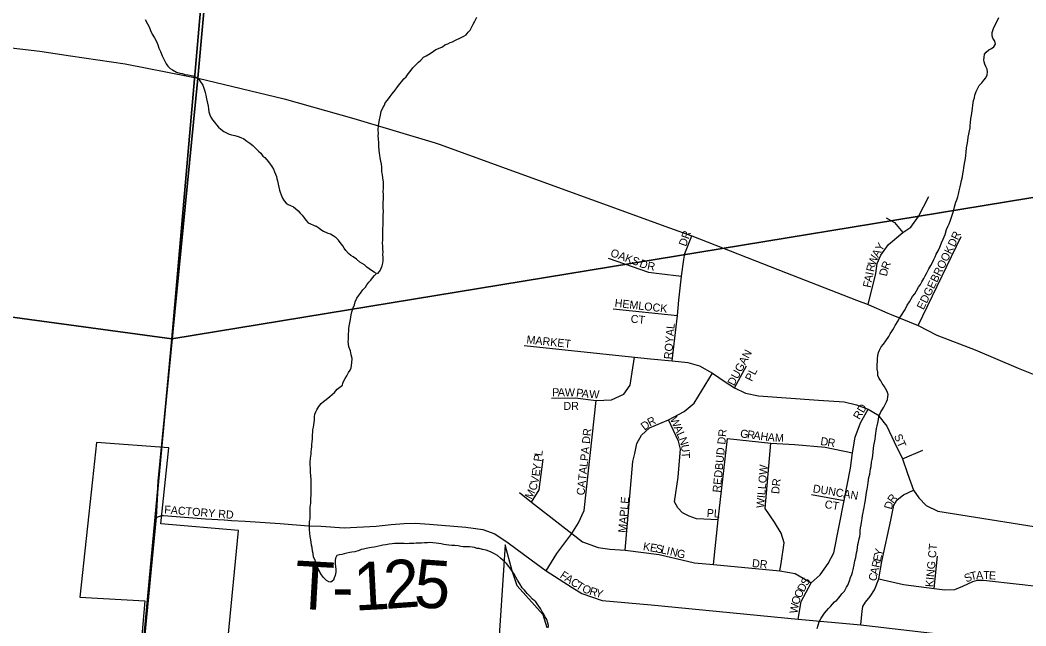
# Model space of a CAD drawing. Extents: x 0 to 1064, y 0 to 440.
# Drawn here: x 203.49 to 222.52, y 369.72 to 381.17 of the extents above; entities that cross this region are included whole.
import ezdxf

# ---------------------------------------------------------------- set-up
doc = ezdxf.new("R2010")
doc.units = 0
for name, color, linetype in [('GM_X_City_Street', 7, 'Continuous'), ('GM_X_City_Street_Text', 7, 'Continuous'), ('GM_X_Corporation', 7, 'Continuous'), ('GM_X_Minor_River', 7, 'Continuous'), ('GM_X_Section', 7, 'Continuous'), ('GM_X_State_Route', 7, 'Continuous'), ('GM_X_Township', 7, 'Continuous'), ('GM_X_Township_Road', 7, 'Continuous'), ('GM_X_Township_Road_Text', 7, 'Continuous')]:
    doc.layers.add(name, color=color, linetype=linetype)

msp = doc.modelspace()

# ---------------------------------------------------------------- linework, layer by layer
at = {"layer": 'GM_X_City_Street'}
for points in [[(206.883, 380.385), (207.047, 382.236), (207.264, 384.616)], [(206.856, 380.071), (206.883, 380.385)], [(219.537, 375.79), (219.682, 376.377), (219.704, 376.567), (219.779, 376.725), (219.921, 376.926), (220.193, 377.153), (220.342, 377.257), (220.489, 377.453), (220.683, 377.833)], [(219.878, 377.431), (220.034, 377.343), (220.193, 377.153)], [(215.83, 374.729), (215.931, 375.582), (215.954, 375.873), (216.002, 376.331), (216.046, 376.645), (216.07, 376.754), (216.199, 377.09)], [(220.48, 375.396), (221.299, 377.078)], [(214.617, 376.667), (215.378, 376.405), (215.583, 376.376), (216.002, 376.331)], [(214.714, 375.71), (215.931, 375.582)], [(213.03, 375.02), (215.114, 374.794), (215.416, 374.763), (215.83, 374.729), (216.127, 374.694), (216.344, 374.631), (216.589, 374.496), (216.833, 374.333), (217.008, 374.216), (217.217, 374.119), (217.462, 374.069), (218.595, 373.983), (219.084, 373.952), (219.317, 373.898), (219.534, 373.812), (219.717, 373.704), (219.887, 373.49), (220.027, 373.199), (220.186, 372.873), (220.283, 372.596), (220.394, 372.283), (220.495, 372.136), (220.636, 371.992), (220.852, 371.888), (222.838, 371.568)], [(213.542, 374.022), (213.992, 374.03), (214.388, 373.976), (214.679, 373.991), (214.912, 374.1), (215.032, 374.268), (215.07, 374.514), (215.114, 374.794)], [(217.008, 374.216), (217.233, 374.635)], [(214.939, 371.146), (215.085, 372.825), (215.119, 372.977), (215.16, 373.168), (215.25, 373.324), (215.401, 373.459), (215.758, 373.615), (216.053, 373.77), (216.247, 373.925), (216.589, 374.496)], [(213.441, 370.76), (213.645, 371.086), (213.928, 371.466), (214.056, 371.664), (214.16, 371.901), (214.388, 373.976)], [(218.211, 369.846), (218.269, 370.176), (218.455, 370.533), (218.626, 370.68), (218.781, 370.894), (218.886, 371.096), (219.084, 372.089), (219.2, 372.699), (219.243, 372.988), (219.289, 373.287), (219.389, 373.558), (219.534, 373.812)], [(216.701, 371.724), (216.286, 371.744), (216.15, 371.79), (216.022, 371.856), (215.933, 371.946), (215.871, 372.061), (215.94, 372.528), (215.967, 372.838), (215.987, 373.056), (215.948, 373.207), (215.758, 373.615)], [(216.612, 370.875), (216.701, 371.724), (216.876, 373.258)], [(216.876, 373.258), (217.695, 373.172), (218.149, 373.149), (218.723, 373.094), (219.243, 372.988)], [(217.868, 370.755), (217.889, 370.899), (217.947, 371.286), (217.889, 371.468), (217.761, 371.678), (217.59, 371.934), (217.695, 373.172)], [(220.186, 372.873), (220.571, 373.038)], [(213.169, 372.058), (213.313, 372.291), (213.384, 372.867)], [(219.398, 369.737), (219.423, 369.993), (219.437, 370.081), (219.484, 370.164), (219.577, 370.271), (219.655, 370.401), (219.736, 370.605), (219.792, 370.933), (219.967, 371.715), (220.023, 372), (220.085, 372.099), (220.204, 372.196), (220.394, 372.283)], [(212.936, 372.237), (213.169, 372.058), (213.701, 371.639), (213.928, 371.466), (214.128, 371.305), (214.427, 371.201), (214.648, 371.17), (214.939, 371.146), (215.579, 371.065), (216.251, 370.909), (216.612, 370.875), (217.868, 370.755), (218.153, 370.708), (218.455, 370.533)], [(218.463, 372.198), (219.084, 372.089)], [(206.203, 371.801), (207, 371.744), (207.349, 371.721)], [(212.727, 371.29), (213.16, 370.968), (213.441, 370.76), (213.938, 370.44), (214.116, 370.327), (214.501, 370.199), (215.432, 370.114), (218.211, 369.846), (219.398, 369.737), (221.24, 369.524), (222.354, 369.36), (222.97, 369.308), (223.022, 369.302)], [(220.782, 370.426), (220.848, 371.032)], [(219.736, 370.605), (220.204, 370.498), (220.782, 370.426), (220.988, 370.397), (221.178, 370.407), (221.327, 370.469), (221.514, 370.558), (221.605, 370.582), (221.719, 370.58), (222.395, 370.506), (222.456, 370.499)], [(222.456, 370.499), (223.084, 370.424), (223.105, 370.422)]]:
    msp.add_lwpolyline(points, dxfattribs=at)
at = {"layer": 'GM_X_Corporation'}
for points in [[(207.425, 369.505), (207.622, 371.519), (206.153, 371.646), (206.304, 373.08), (204.937, 373.184), (204.859, 372.476), (204.62, 370.26), (205.847, 370.19), (205.364, 364.533)], [(213.461, 369.682), (213.385, 369.928), (212.894, 370.475), (212.8, 370.759), (212.668, 371.25), (212.523, 369.059)]]:
    msp.add_lwpolyline(points, dxfattribs=at)
at = {"layer": 'GM_X_Minor_River'}
for points in [[(210.255, 376.373), (210.287, 376.415), (210.318, 376.463), (210.338, 376.523), (210.351, 376.572), (210.359, 376.626), (210.36, 376.681), (210.356, 376.736), (210.357, 376.785), (210.352, 376.834), (210.353, 376.894), (210.349, 376.961), (210.35, 377.01), (210.353, 377.101), (210.354, 377.144), (210.356, 377.217), (210.358, 377.302), (210.359, 377.345), (210.361, 377.424), (210.362, 377.485), (210.364, 377.546), (210.36, 377.625), (210.361, 377.68), (210.362, 377.722), (210.364, 377.789), (210.366, 377.868), (210.362, 377.935), (210.363, 377.984), (210.365, 378.069), (210.366, 378.112), (210.356, 378.179), (210.345, 378.252), (210.335, 378.301), (210.336, 378.35), (210.331, 378.393), (210.326, 378.447), (210.315, 378.503), (210.305, 378.564), (210.294, 378.613), (210.289, 378.655), (210.284, 378.71), (210.28, 378.777), (210.276, 378.851), (210.271, 378.924), (210.267, 378.979), (210.268, 379.027), (210.263, 379.088), (210.272, 379.179), (210.287, 379.282), (210.307, 379.373), (210.321, 379.44), (210.353, 379.512), (210.385, 379.56), (210.398, 379.602), (210.442, 379.656), (210.492, 379.722), (210.53, 379.776), (210.587, 379.847), (210.631, 379.907), (210.675, 379.961), (210.706, 380.003), (210.75, 380.056), (210.794, 380.098), (210.832, 380.152), (210.869, 380.199), (210.92, 380.265), (210.97, 380.319), (211.026, 380.372), (211.075, 380.413), (211.125, 380.467), (211.175, 380.49), (211.249, 380.537), (211.311, 380.578), (211.354, 380.613), (211.409, 380.63), (211.483, 380.665), (211.527, 380.7), (211.582, 380.717), (211.625, 380.747), (211.668, 380.758), (211.729, 380.787), (211.822, 380.833), (211.883, 380.862), (211.927, 380.891), (211.97, 380.939), (212.008, 380.98), (212.04, 381.041), (212.065, 381.089), (212.091, 381.149), (212.13, 381.221)], [(221.158, 377.585), (221.171, 377.64), (221.198, 377.724), (221.211, 377.773), (221.231, 377.827), (221.244, 377.875), (221.258, 377.942), (221.278, 378.015), (221.292, 378.075), (221.305, 378.136), (221.319, 378.208), (221.327, 378.263), (221.34, 378.323), (221.348, 378.378), (221.355, 378.42), (221.363, 378.487), (221.377, 378.554), (221.384, 378.608), (221.392, 378.675), (221.4, 378.754), (221.408, 378.815), (221.422, 378.888), (221.429, 378.954), (221.443, 379.015), (221.451, 379.076), (221.464, 379.13), (221.465, 379.173), (221.473, 379.227), (221.481, 379.306), (221.489, 379.367), (221.496, 379.409), (221.503, 379.452), (221.51, 379.5), (221.518, 379.561), (221.525, 379.603), (221.532, 379.646), (221.546, 379.7), (221.553, 379.749), (221.579, 379.821), (221.605, 379.869), (221.637, 379.929), (221.687, 379.983), (221.724, 380.031), (221.762, 380.078), (221.788, 380.132), (221.795, 380.187), (221.785, 380.242), (221.761, 380.291), (221.744, 380.334), (221.733, 380.377), (221.728, 380.42), (221.729, 380.463), (221.737, 380.523), (221.768, 380.565), (221.818, 380.607), (221.873, 380.63), (221.917, 380.665), (221.948, 380.713), (221.932, 380.768), (221.897, 380.83), (221.88, 380.873), (221.881, 380.934), (221.907, 381.012), (221.94, 381.078), (221.965, 381.126), (222.01, 381.217)], [(205.854, 381.182), (205.901, 381.095), (205.93, 381.04), (205.959, 380.972), (205.988, 380.905), (206.035, 380.831), (206.076, 380.751), (206.104, 380.683), (206.116, 380.64), (206.144, 380.573), (206.179, 380.493)], [(206.179, 380.493), (206.208, 380.432), (206.225, 380.389), (206.255, 380.339), (206.284, 380.296), (206.326, 380.253), (206.374, 380.227), (206.446, 380.183), (206.512, 380.163), (206.56, 380.156), (206.609, 380.143), (206.669, 380.136), (206.723, 380.122), (206.766, 380.115), (206.814, 380.09), (206.856, 380.065), (206.891, 380.021), (206.944, 379.941), (206.961, 379.898), (206.978, 379.843), (206.99, 379.8), (207.001, 379.751), (207.017, 379.678), (207.034, 379.598), (207.045, 379.543), (207.056, 379.488), (207.06, 379.433), (207.077, 379.378), (207.101, 379.335), (207.13, 379.28), (207.165, 379.236), (207.207, 379.187), (207.242, 379.143), (207.29, 379.106), (207.344, 379.062), (207.392, 379.037), (207.446, 379.011), (207.488, 378.998), (207.554, 378.984), (207.615, 378.971), (207.663, 378.952), (207.723, 378.926), (207.777, 378.882), (207.837, 378.844), (207.89, 378.801), (207.938, 378.751), (208.003, 378.689), (208.045, 378.651), (208.08, 378.596), (208.122, 378.57), (208.157, 378.527), (208.211, 378.465), (208.252, 378.403), (208.281, 378.348), (208.304, 378.299), (208.322, 378.256), (208.339, 378.213), (208.344, 378.17), (208.361, 378.127), (208.372, 378.066), (208.383, 378.011), (208.4, 377.956), (208.411, 377.913), (208.428, 377.864), (208.457, 377.803), (208.487, 377.753), (208.522, 377.71), (208.564, 377.685), (208.606, 377.665), (208.66, 377.64), (208.702, 377.609), (208.75, 377.565), (208.791, 377.521), (208.827, 377.478), (208.862, 377.429), (208.897, 377.385), (208.939, 377.336), (209.086, 377.273)], [(219.415, 371.707), (219.422, 371.749), (219.429, 371.804), (219.443, 371.858), (219.45, 371.9), (219.458, 371.955), (219.472, 372.028), (219.485, 372.094), (219.493, 372.149), (219.5, 372.197), (219.507, 372.24), (219.515, 372.3), (219.529, 372.379), (219.536, 372.428), (219.551, 372.525), (219.565, 372.585), (219.58, 372.688), (219.593, 372.731), (219.601, 372.81), (219.614, 372.864), (219.622, 372.931), (219.631, 373.016), (219.638, 373.07), (219.645, 373.125), (219.653, 373.186), (219.667, 373.246), (219.674, 373.307), (219.682, 373.355), (219.689, 373.404), (219.696, 373.446), (219.704, 373.501), (219.724, 373.579), (219.731, 373.622), (219.738, 373.67), (219.758, 373.719), (219.777, 373.761), (219.803, 373.803), (219.834, 373.851), (219.86, 373.899), (219.885, 373.953), (219.899, 373.995), (219.906, 374.044), (219.913, 374.092), (219.896, 374.147), (219.867, 374.203), (219.838, 374.246), (219.803, 374.296), (219.774, 374.351), (219.745, 374.395), (219.722, 374.45), (219.717, 374.511), (219.707, 374.572), (219.708, 374.615), (219.709, 374.657), (219.71, 374.712), (219.712, 374.767), (219.719, 374.827), (219.733, 374.888), (219.752, 374.93), (219.784, 374.99), (219.828, 375.044), (219.872, 375.104), (219.929, 375.187), (219.955, 375.235), (220.005, 375.313), (220.031, 375.355), (220.05, 375.397), (220.101, 375.481), (220.126, 375.529), (220.164, 375.589), (220.221, 375.679), (220.247, 375.721), (220.273, 375.781), (220.317, 375.841), (220.374, 375.943), (220.418, 375.997), (220.45, 376.051), (220.488, 376.117), (220.526, 376.171), (220.551, 376.219), (220.589, 376.285), (220.615, 376.333), (220.64, 376.381), (220.685, 376.465), (220.723, 376.531), (220.761, 376.597), (220.781, 376.645), (220.806, 376.693), (220.826, 376.741), (220.858, 376.808), (220.89, 376.874), (220.923, 376.958), (220.955, 377.03), (220.994, 377.115), (221.02, 377.211), (221.046, 377.266), (221.066, 377.32), (221.091, 377.368), (221.118, 377.459), (221.144, 377.537), (221.158, 377.585)], [(210.049, 376.165), (210.087, 376.213), (210.124, 376.255), (210.156, 376.297), (210.193, 376.338), (210.231, 376.38), (210.189, 376.405), (210.141, 376.437), (210.093, 376.469), (210.052, 376.5), (210.004, 376.544), (209.962, 376.569), (209.92, 376.595), (209.855, 376.651), (209.789, 376.695), (209.747, 376.721), (209.706, 376.758), (209.652, 376.815), (209.623, 376.858), (209.594, 376.901), (209.547, 376.963), (209.511, 377.007), (209.47, 377.05), (209.416, 377.088), (209.362, 377.12), (209.32, 377.133), (209.278, 377.153), (209.23, 377.172), (209.182, 377.204), (209.14, 377.235), (209.086, 377.273), (209.082, 377.277)], [(209.328, 370.547), (209.287, 370.573), (209.227, 370.635), (209.192, 370.685), (209.163, 370.734), (209.14, 370.777), (209.117, 370.82), (209.105, 370.863), (209.082, 370.919), (209.066, 370.974), (209.042, 371.017), (209.032, 371.084), (209.021, 371.127), (209.017, 371.2), (209.006, 371.243), (208.995, 371.298), (208.99, 371.347), (208.979, 371.408), (208.969, 371.469), (208.964, 371.536), (208.966, 371.579), (208.967, 371.634), (208.968, 371.688), (208.976, 371.743), (208.978, 371.822), (208.979, 371.883), (208.981, 371.962), (208.989, 372.035), (208.991, 372.114), (208.994, 372.205), (208.996, 372.29), (208.997, 372.345), (208.999, 372.394), (208.994, 372.442), (208.995, 372.485), (208.99, 372.552), (208.986, 372.625), (208.982, 372.698), (208.977, 372.759), (208.979, 372.814), (208.987, 372.887), (208.995, 372.966), (208.996, 373.008), (209.003, 373.057), (209.01, 373.099), (209.012, 373.148), (209.013, 373.197), (209.02, 373.251), (209.022, 373.33), (209.03, 373.379), (209.031, 373.421), (209.038, 373.476), (209.053, 373.561), (209.06, 373.609), (209.061, 373.67), (209.069, 373.719), (209.082, 373.761), (209.101, 373.803), (209.139, 373.863), (209.189, 373.923), (209.233, 373.958), (209.283, 373.999), (209.351, 374.052), (209.394, 374.088), (209.438, 374.129), (209.488, 374.189), (209.538, 374.23), (209.587, 374.266), (209.595, 374.308), (209.614, 374.35), (209.639, 374.392), (209.671, 374.446), (209.703, 374.506), (209.734, 374.548), (209.754, 374.596), (209.768, 374.687), (209.771, 374.772), (209.754, 374.84), (209.738, 374.919), (209.709, 374.993), (209.705, 375.048), (209.7, 375.091), (209.701, 375.133), (209.702, 375.194), (209.703, 375.237), (209.711, 375.291), (209.712, 375.346), (209.72, 375.413), (209.741, 375.51), (209.748, 375.552), (209.755, 375.595), (209.769, 375.655), (209.789, 375.728), (209.815, 375.788), (209.828, 375.842), (209.86, 375.915), (209.892, 375.956), (209.93, 376.004), (209.974, 376.07), (210.024, 376.123), (210.049, 376.165)], [(218.572, 369.665), (218.592, 369.731), (218.612, 369.791), (218.644, 369.864), (218.682, 369.917), (218.707, 369.959), (218.745, 370.001), (218.783, 370.043), (218.826, 370.084), (218.864, 370.126), (218.901, 370.174), (218.945, 370.203), (218.989, 370.251), (219.039, 370.322), (219.089, 370.376), (219.127, 370.448), (219.153, 370.49), (219.185, 370.568), (219.205, 370.629), (219.225, 370.689), (219.238, 370.731), (219.251, 370.78), (219.272, 370.87), (219.286, 370.949), (219.3, 371.01), (219.314, 371.1), (219.327, 371.143), (219.342, 371.258), (219.356, 371.3), (219.369, 371.361), (219.377, 371.409), (219.384, 371.458), (219.385, 371.513), (219.393, 371.573), (219.401, 371.628), (219.415, 371.707)], [(213.484, 369.683), (213.485, 369.725), (213.468, 369.792), (213.457, 369.835), (213.416, 369.897), (213.399, 369.94), (213.37, 369.984), (213.335, 370.045), (213.305, 370.089), (213.27, 370.132), (213.247, 370.175), (213.187, 370.225), (213.134, 370.282), (213.087, 370.331), (213.033, 370.394), (212.992, 370.437), (212.945, 370.511), (212.904, 370.579), (212.87, 370.641), (212.846, 370.69), (212.811, 370.734), (212.776, 370.79), (212.735, 370.839), (212.694, 370.895), (212.628, 370.952), (212.581, 370.995), (212.521, 371.045), (212.455, 371.084), (212.389, 371.116), (212.311, 371.148), (212.238, 371.162), (212.178, 371.182), (212.135, 371.183), (212.087, 371.196), (212.045, 371.203), (211.99, 371.211), (211.917, 371.213), (211.875, 371.214), (211.826, 371.221), (211.778, 371.228), (211.717, 371.236), (211.657, 371.238), (211.602, 371.245), (211.554, 371.252), (211.505, 371.254), (211.457, 371.267), (211.408, 371.274), (211.36, 371.281), (211.299, 371.289), (211.244, 371.291), (211.196, 371.286), (211.141, 371.287), (211.086, 371.282), (211.031, 371.278), (210.983, 371.279), (210.94, 371.274), (210.897, 371.275), (210.849, 371.276), (210.806, 371.271), (210.758, 371.272), (210.709, 371.273), (210.666, 371.275), (210.618, 371.276), (210.575, 371.277), (210.532, 371.266), (210.471, 371.261), (210.41, 371.251), (210.355, 371.24), (210.3, 371.229), (210.245, 371.218), (210.19, 371.207), (210.141, 371.196), (210.099, 371.191), (210.038, 371.181), (209.989, 371.17), (209.946, 371.159), (209.903, 371.142), (209.823, 371.119), (209.768, 371.108), (209.726, 371.103), (209.671, 371.093), (209.622, 371.082), (209.579, 371.064), (209.536, 371.059), (209.481, 371.049), (209.455, 370.995), (209.454, 370.952), (209.453, 370.897), (209.457, 370.836), (209.462, 370.787), (209.461, 370.733), (209.453, 370.672), (209.434, 370.624), (209.42, 370.582), (209.371, 370.546), (209.328, 370.547)]]:
    msp.add_lwpolyline(points, dxfattribs=at)
at = {"layer": 'GM_X_Section'}
for points in [[(225.477, 394.528), (223.805, 378.004), (206.359, 375.143), (207.791, 391.554)], [(207.791, 391.554), (206.359, 375.143), (190.108, 377.348), (191.472, 393.349)], [(223.805, 378.004), (222.155, 361.074), (204.837, 358.818), (206.359, 375.143)], [(206.359, 375.143), (204.837, 358.818), (188.579, 361.283), (190.108, 377.348)]]:
    msp.add_lwpolyline(points, close=True, dxfattribs=at)
at = {"layer": 'GM_X_State_Route'}
for points in [[(201.12, 380.912), (202.616, 380.728), (203.862, 380.581), (204.443, 380.491), (205.477, 380.34), (206.693, 380.103)], [(206.693, 380.103), (206.856, 380.071), (208.489, 379.677), (209.807, 379.309), (211.345, 378.846)], [(211.345, 378.846), (211.416, 378.824), (215.777, 377.241), (216.199, 377.09), (217.97, 376.4)], [(217.97, 376.4), (219.316, 375.876)], [(219.316, 375.876), (219.537, 375.79), (219.909, 375.631)], [(219.909, 375.631), (219.973, 375.604), (220.48, 375.396), (220.833, 375.215), (221.561, 374.934), (222.373, 374.588), (222.881, 374.389), (223.456, 374.131)]]:
    msp.add_lwpolyline(points, dxfattribs=at)
at = {"layer": 'GM_X_Township'}
for points in [[(205.364, 364.533), (206.065, 371.769), (206.1, 372.456), (206.855, 380.071), (207.047, 382.236), (207.432, 386.467), (207.767, 390.13), (207.855, 390.984), (207.909, 391.598), (207.998, 392.224), (208.112, 392.813), (208.274, 393.604), (208.358, 394.055), (208.416, 394.339)], [(208.416, 394.339), (208.358, 394.055), (208.274, 393.604), (208.112, 392.813), (207.998, 392.224), (207.909, 391.598), (207.855, 390.984), (207.767, 390.13), (207.432, 386.467), (207.047, 382.236), (206.855, 380.071), (206.1, 372.456), (206.065, 371.769), (205.364, 364.533)]]:
    msp.add_lwpolyline(points, dxfattribs=at)
at = {"layer": 'GM_X_Township_Road'}
for points in [[(206.065, 371.769), (206.1, 372.456)], [(205.255, 363.253), (205.262, 363.458), (205.364, 364.533), (206.065, 371.769)], [(206.065, 371.769), (206.166, 371.804), (206.203, 371.801)], [(207.349, 371.721), (207.492, 371.712)], [(207.492, 371.712), (207.749, 371.695), (208.411, 371.653), (208.947, 371.607), (209.183, 371.603), (209.619, 371.572), (210.227, 371.603), (210.509, 371.631), (210.754, 371.655), (210.971, 371.657), (211.233, 371.639), (211.923, 371.581), (212.246, 371.538), (212.475, 371.457), (212.727, 371.29)]]:
    msp.add_lwpolyline(points, dxfattribs=at)

# ---------------------------------------------------------------- texts
at = {"layer": 'GM_X_City_Street_Text'}
for s, height, rotation, p in [('DR', 0.1515, 70.5566, (216.089, 376.879)), ('DR', 0.1515, 64.7982, (221.171, 376.868)), ('OAKS', 0.1515, 340.1437, (214.646, 376.71)), ('Y', 0.152, 57.6981, (219.79, 376.784)), ('EDGEBROOK', 0.1515, 63.7355, (220.584, 375.682)), ('D', 0.152, 339.8787, (215.195, 376.509)), ('W', 0.152, 69.5817, (219.667, 376.513)), ('A', 0.152, 60.5018, (219.725, 376.67)), ('R', 0.152, 349.312, (215.346, 376.456)), ('R', 0.152, 78.1755, (219.644, 376.401)), ('D', 0.152, 77.3313, (219.888, 376.317)), ('R', 0.152, 67.4138, (219.915, 376.44)), ('F', 0.152, 78.1916, (219.582, 376.101)), ('A', 0.152, 78.18, (219.603, 376.206)), ('I', 0.152, 78.1437, (219.631, 376.336)), ('HEMLOCK', 0.1515, 353.3902, (214.733, 375.751)), ('CT', 0.1515, 353.6638, (215.037, 375.452)), ('ROYAL', 0.1515, 85.2348, (215.821, 374.752)), ('MARKET', 0.1515, 354.0899, (213.066, 375.058)), ('DUGAN', 0.1515, 61.8592, (216.998, 374.243)), ('PL', 0.1515, 63.4349, (217.335, 374.327)), ('P', 0.152, 359.9454, (213.556, 374.058)), ('A', 0.152, 359.9126, (213.663, 374.058)), ('W', 0.152, 359.5629, (213.796, 374.058)), ('P', 0.152, 353.5391, (214.005, 374.054)), ('A', 0.152, 352.856, (214.111, 374.042)), ('W', 0.152, 357.2196, (214.255, 374.025)), ('DR', 0.1515, 0, (213.77, 373.8)), ('RD', 0.1515, 59.5361, (219.372, 373.604)), ('D', 0.152, 38.4482, (215.307, 373.405)), ('R', 0.152, 26.8583, (215.405, 373.484)), ('W', 0.152, 294.0376, (215.782, 373.628)), ('CATALPA DR', 0.1515, 84.095, (214.168, 372.179)), ('A', 0.152, 294.0224, (215.853, 373.47)), ('L', 0.152, 293.9986, (215.907, 373.348)), ('REDBUD DR', 0.1515, 84.2867, (216.741, 372.232)), ('G', 0.152, 352.284, (217.107, 373.284)), ('R', 0.152, 352.2545, (217.239, 373.266)), ('A', 0.152, 352.258, (217.358, 373.25)), ('N', 0.152, 289.0776, (215.949, 373.254)), ('H', 0.152, 352.2407, (217.49, 373.232)), ('A', 0.152, 354.5982, (217.629, 373.214)), ('M', 0.152, 356.9863, (217.768, 373.201)), ('D', 0.152, 351.975, (218.626, 373.138)), ('R', 0.152, 350.0905, (218.757, 373.119)), ('ST', 0.1515, 293.2005, (220.022, 373.307)), ('L', 0.152, 82.7469, (213.367, 372.922)), ('U', 0.152, 278.025, (215.991, 373.135)), ('P', 0.152, 82.7469, (213.354, 372.816)), ('T', 0.152, 271.2299, (216.009, 373.008)), ('E', 0.152, 82.7469, (213.318, 372.538)), ('Y', 0.152, 82.7469, (213.332, 372.644)), ('WILLOW', 0.1515, 85.1548, (217.568, 371.938)), ('V', 0.152, 78.8784, (213.291, 372.396)), ('DR', 0.1515, 83.9934, (217.851, 372.205)), ('M', 0.152, 63.4046, (213.166, 372.098)), ('C', 0.152, 71.1415, (213.246, 372.261)), ('DUNCAN', 0.1515, 350.3852, (218.481, 372.244)), ('MAPLE', 0.1515, 85.134, (214.956, 371.472)), ('CT', 0.1515, 350.5416, (218.705, 371.947)), ('D', 0.152, 74.7334, (219.98, 371.909)), ('R', 0.152, 53.8584, (220.009, 372.024)), ('FACTORY RD', 0.1515, 355.4504, (206.212, 371.844)), ('PL', 0.1515, 356.4254, (216.478, 371.778)), ('K', 0.152, 350.4694, (215.268, 371.151)), ('E', 0.152, 350.4795, (215.399, 371.129)), ('S', 0.152, 349.3921, (215.504, 371.111)), ('L', 0.152, 347.2163, (215.607, 371.092)), ('I', 0.152, 346.8546, (215.711, 371.069)), ('N', 0.152, 346.7695, (215.775, 371.053)), ('G', 0.152, 346.7787, (215.905, 371.023)), ('Y', 0.152, 77.4593, (219.795, 371.028)), ('KING CT', 0.1515, 84.8967, (220.768, 370.445)), ('DR', 0.1515, 353.9946, (217.333, 370.831)), ('R', 0.152, 77.4672, (219.746, 370.807)), ('E', 0.152, 77.4741, (219.772, 370.924)), ('F', 0.152, 326.416, (213.692, 370.64)), ('A', 0.152, 77.1231, (219.716, 370.676)), ('T', 0.152, 12.3925, (221.484, 370.577)), ('A', 0.152, 2.0984, (221.581, 370.599)), ('T', 0.152, 357.5401, (221.711, 370.604)), ('E', 0.152, 357.0475, (221.817, 370.599)), ('A', 0.152, 326.4498, (213.781, 370.581)), ('C', 0.152, 326.4447, (213.892, 370.507)), ('T', 0.152, 326.5376, (213.992, 370.44)), ('S', 0.152, 60.4517, (218.381, 370.463)), ('C', 0.152, 72.9472, (219.678, 370.55)), ('S', 0.152, 25.111, (221.396, 370.534)), ('O', 0.152, 338.075, (214.111, 370.366)), ('R', 0.152, 343.5953, (214.25, 370.311)), ('Y', 0.152, 343.7608, (214.365, 370.277)), ('O', 0.152, 62.9072, (218.259, 370.228)), ('D', 0.152, 62.0857, (218.319, 370.346)), ('O', 0.152, 73.2589, (218.223, 370.107)), ('W', 0.152, 80.2004, (218.195, 369.941))]:
    msp.add_text(s, height=height, rotation=rotation, dxfattribs=at).set_placement(p)
at = {"layer": 'GM_X_Township_Road_Text'}
for s, rotation, p in [('T', 356.7412, (208.662, 370.047)), ('1', 3.0077, (209.822, 370.005)), ('2', 4.1646, (210.401, 370.036)), ('5', 355.9585, (210.926, 370.077)), ('-', 359.6247, (209.39, 370.007))]:
    msp.add_text(s, height=0.909, rotation=rotation, dxfattribs=at).set_placement(p)

doc.saveas('drawing.dxf')
